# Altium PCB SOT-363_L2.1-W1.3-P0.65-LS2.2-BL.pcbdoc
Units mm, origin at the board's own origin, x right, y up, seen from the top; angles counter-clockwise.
Board outline 15.2 x 15.53 mm, 2 copper layers (Top Layer, Bottom Layer), stack 0 mm thick; 1 components, 0 nets, 6 pads, 0 vias.
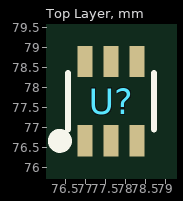
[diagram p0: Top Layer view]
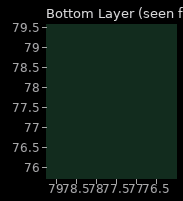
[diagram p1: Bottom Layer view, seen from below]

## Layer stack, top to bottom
Top Layer: signal copper (thickness not stored)
Bottom Layer: signal copper (thickness not stored)

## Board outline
85.054,69.85 69.85,69.85 69.85,85.38 85.054,85.38

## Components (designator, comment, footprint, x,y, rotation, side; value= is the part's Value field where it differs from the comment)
U? "" SOT-363_L2.1-W1.3-P0.65-LS2.2-BL 77.628,77.65 r0 top

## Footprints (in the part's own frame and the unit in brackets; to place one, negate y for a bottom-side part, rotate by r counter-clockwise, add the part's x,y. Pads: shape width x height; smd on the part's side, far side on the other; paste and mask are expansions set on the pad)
SOT-363_L2.1-W1.3-P0.65-LS2.2-BL [mm]
  rect 0.38x0.78 smd: 1(-0.65,-0.99) 2(0,-0.99) 3(0.65,-0.99) 4(0.65,0.99) 5(0,0.99) 6(-0.65,0.99)
  silkscreen extent -1.43,-1.14 1.08,0.7

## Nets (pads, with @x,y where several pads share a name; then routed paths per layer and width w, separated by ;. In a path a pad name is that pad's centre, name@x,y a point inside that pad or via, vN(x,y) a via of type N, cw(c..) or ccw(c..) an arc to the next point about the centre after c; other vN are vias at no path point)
pads on no net: U?.1 U?.2 U?.3 U?.4 U?.5 U?.6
